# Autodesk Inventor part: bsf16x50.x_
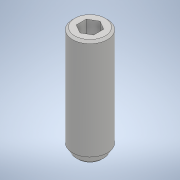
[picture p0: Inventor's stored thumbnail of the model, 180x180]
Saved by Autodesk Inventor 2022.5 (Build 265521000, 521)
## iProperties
Created: 2020-01
Part Number: bsf16x50.x_
Material: 一般
Document SubType Name: Modeling
Designer: ImaoCorp
Density: 1 g/cm^3
Appearance: 既定
Sending System: SOLIDWORKS 2018-2018316
MC: AMD64
MC_MODEL: Intel64 Family 6 Model 60 Stepping 3, GenuineIntel
OS: Windows_NT
FRU: Parasolid Version 30.0, build 310,  6- 8-2018
FORMAT: text
GUISE: transmit
KEY: bsf16x50
FILE: bsf16x50.x_t
DATE: Thu Jan 23 16:49:02 2020
Author: ImaoCorp
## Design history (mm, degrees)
feature "Base1"
node "ソリッド1"
